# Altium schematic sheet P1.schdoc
size 297 x 209 mm; Symbol: Drawing-Symbol_A4; @Project Name: DicePopper; @Page Count: 1; @Update Date: 2026-11-07; @Create Date: 2026-11-07; @Schematic Name: Schematic1; @Page No: 1; @Page Name: P1; Company: EasyEDA.com; Version: V1.0; Page Size: A4; Device: Drawing-Symbol_A4; @Create Time: 12:54:06; @Update Time: 12:54:06; Border: 1; Width: 1170; Height: 825; Region Start: 1; X Region Count: 6; Y Region Count: 4; Blade Width: 10; Title Block Position: 3; @Board Name: Board1
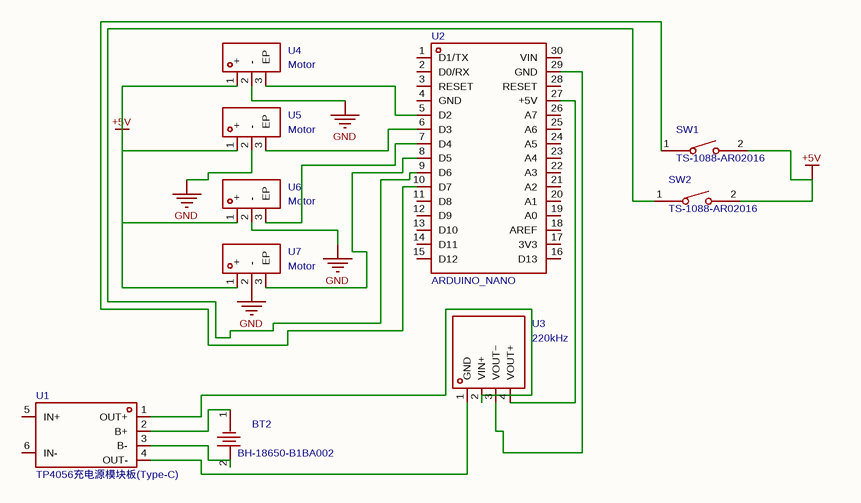
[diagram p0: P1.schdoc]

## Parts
BT2  BH-18650-B1BA002  [BATTERY-SMD_18650-1S-L77.1-W20.7-1]
SW1  TS-1088-AR02016  [SW-SMD_L3.9-W3.0-P4.45]
SW2  TS-1088-AR02016  [SW-SMD_L3.9-W3.0-P4.45]
U1  TP4056充电源模块板(Type-C)  [PWRM-TH_TP4056]
U2  ARDUINO_NANO  [COMM-TH_ARDUINO_NANO]
U3  220kHz  [PWRM-TH_4P-L11.5-W6.0-P2.54_ZY0305FM-1W]
U4  Motor  [VIBRATING-MOTOR-SMD_3P-C9900001680]
U5  Motor  [VIBRATING-MOTOR-SMD_3P-C9900001680]
U6  Motor  [VIBRATING-MOTOR-SMD_3P-C9900001680]
U7  Motor  [VIBRATING-MOTOR-SMD_3P-C9900001680]

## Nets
+5V: SW1.2 SW2.2 U4.1(+) U5.1(+) U6.1(+) U7.1(+)
GND: U4.2(-) U5.2(-) U6.2(-) U7.2(-)
NetBT2_1: BT2.1 U1.2(B+)
NetBT2_2: BT2.2 U1.3(B-)
NetSW1_1: SW1.1 U2.10(D7)
NetSW2_1: SW2.1 U2.9(D6)
NetU1_1: U1.1(OUT+) U3.2(VIN+)
NetU1_4: U1.4(OUT-) U3.1(GND)
NetU2_5: U2.5(D2) U4.3(EP)
NetU2_6: U2.6(D3) U5.3(EP)
NetU2_7: U2.7(D4) U6.3(EP)
NetU2_8: U2.8(D5) U7.3(EP)
NetU2_27: U2.27(+5V) U3.4(VOUT+)
NetU2_29: U2.29(GND) U3.3(VOUT−)

Not connected (* = marked no-connect by the designer): U1 5(IN+) 6(IN-); U2 1(D1/TX) 2(D0/RX) 3(RESET) 4(GND) 11(D8) 12(D9) 13(D10) 14(D11) 15(D12) 16(D13) 17(3V3) 18(AREF) 19(A0) 20(A1) 21(A2) 22(A3) 23(A4) 24(A5) 25(A6) 26(A7) 28(RESET) 30(VIN)

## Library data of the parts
BT2 = BH-18650-B1BA002: Type:Battery holder Operating Temperature:-25~85℃ Contact material:Phosphor bronze Contact coating:Gold plating Applicable battery specifications:18650; Manufacturer: MYOUNG(美阳); AddInBom: yes; ModelId: 2067da811af9495aaa526018591150860819f05c4eef4c71ace90d822a990e87; ModelTransform: 812.9905,3387.00102,0,0,0,0,0,0,-59.055; Applicable battery specifications: 18650
SW1 SW2 = TS-1088-AR02016: Circuit:SPST Actuator Style:Round Button Operating Force:1.6N Mounting Type:Surface Mount,Vertical Length:3.9mm Width:3mm Switch Height:2mm with Bracket:Without Bracket Contact Current:50mA Voltage Rating:12V Actuator/Cap Color:Black With Lamp:- IP Rating; Manufacturer: XUNPU(讯普); AddInBom: yes; ModelId: 305d1c5953df46c2be38ec48c2aa18760819f05c4eef4c71ace90d822a990e87; ModelName: SW-SMD_L3.9-W2.9-H2.0-LS4.8; ModelTransform: 188.976,114.174,0,0,0,0,0,0,0; Circuit: SPST; Operating Force: 1.6N; Switch Height: 2mm; Contact Current: 50mA; Voltage Rating: 12V; Actuator/Cap Color: Black; Life: 100,000 cycles
U1 = TP4056充电源模块板(Type-C): AddInBom: yes
U2 = ARDUINO_NANO: AddInBom: yes; ModelId: 47918d8faaf14d6297ccdfaa42e0b89d0819f05c4eef4c71ace90d822a990e87; ModelTransform: 699.9986,1784.14604,0,270,0,0,-42.323,0,-137.795
U3 = ISOLATED DC-DC Converter AIDC5V5V200MATH: Type:- Number of Outputs:- Output Power:1W Voltage - Supply:4.5V~5.5V Voltage - Supply:4.5V~5.5V Conversion Efficiency:77% Conversion Efficiency:77% Output Voltage:5V Output Voltage:5V Output Current(Max):200mA Output Current(Max):200mA Capacitive Load(Ma; Manufacturer: Analog; AddInBom: yes; Output Power: 1W; Conversion Efficiency: 77%; Output Voltage: 5V; Output Current(Max): 200mA; Capacitive Load(Max): 470uF; Isolation Voltage(Vrms): 1.5kV; Ripple Noise: 75mVp-p
U4-U7 = Motor: Symbol: MOTOR_C9900020557; AddInBom: yes; ModelId: c6deb1d4c3154f218e554dbafbda0d190819f05c4eef4c71ace90d822a990e87; ModelTransform: 173.04154,413.385,0,270,0,0,-107.283,0,0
